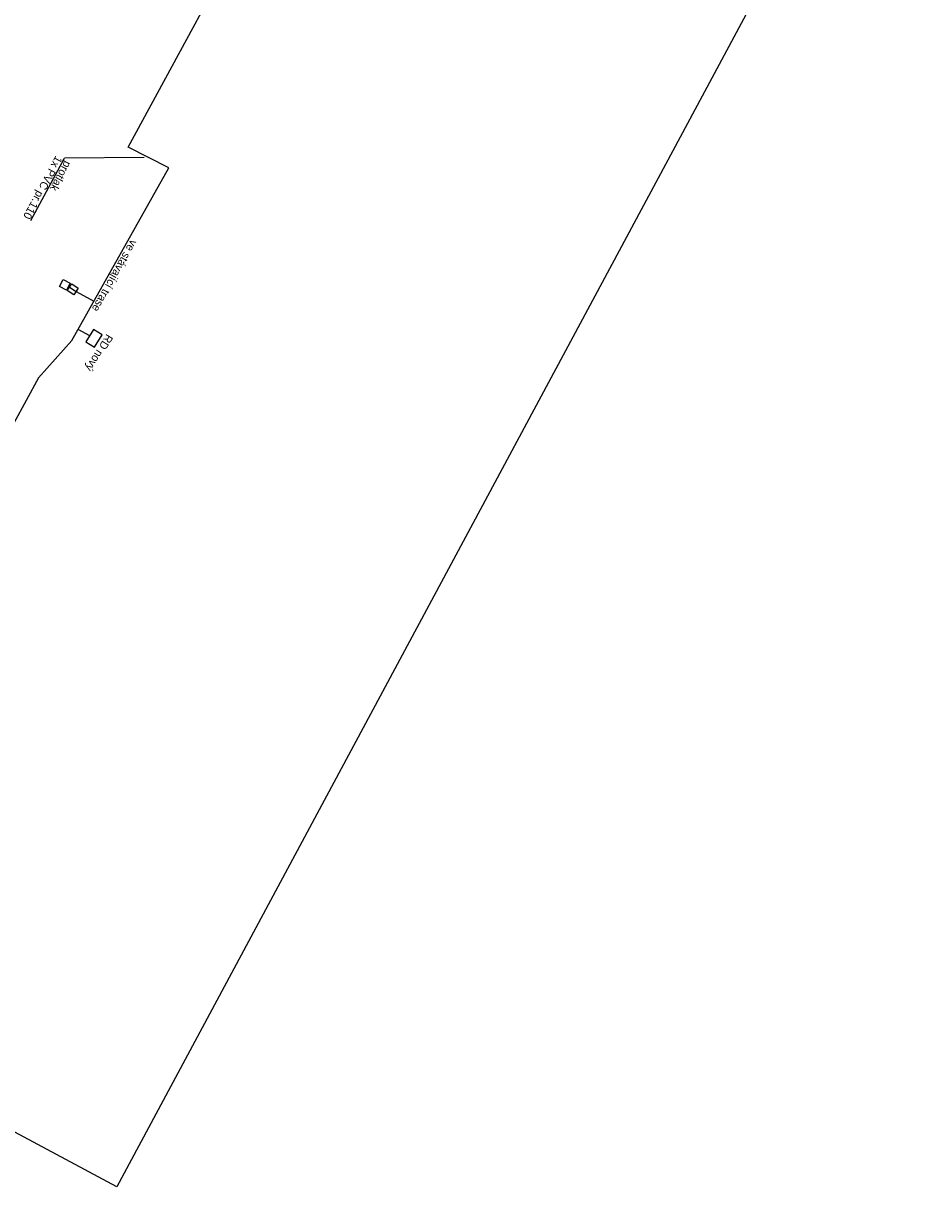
# Model space of a CAD drawing. Extents: x -795110 to -794650, y -1135846 to -1134690.
# Drawn here: x -794871.7 to -794649.8, y -1135200.1 to -1134909.4 of the extents above; entities that cross this region are included whole.
import ezdxf

# ---------------------------------------------------------------- set-up
doc = ezdxf.new("R2010")
doc.units = 0
for name, color, linetype in [('Kabelová trasa', 7, 'Continuous'), ('Popis trasy', 7, 'Continuous'), ('Prvky_zab_zar', 7, 'Continuous'), ('Ramecky', 7, 'Continuous'), ('Vrstva 3', 7, 'Continuous')]:
    doc.layers.add(name, color=color, linetype=linetype)

msp = doc.modelspace()

# ---------------------------------------------------------------- linework, layer by layer
at = {"layer": 'Kabelová trasa'}
for p, q in [((-794855.08, -1134987.47), (-794858.01, -1134985.89)), ((-794859.57, -1134988.66), (-794867.89, -1134997.98)), ((-794867.89, -1134997.98), (-794877.13, -1135014.95))]:
    msp.add_line(p, q, dxfattribs=at)
for points in [[(-794859.57, -1134988.66), (-794835.3, -1134945.55), (-794845.51, -1134940.37), (-794776.44, -1134813), (-794772.18, -1134815.08)], [(-794860.41, -1134975.21), (-794860.15, -1134975.35), (-794858.49, -1134976.45), (-794854.05, -1134978.87)]]:
    msp.add_lwpolyline(points, dxfattribs=at)
at = {"layer": 'Popis trasy'}
for p in [(-794869.76, -1134958.68), (-794841.5, -1134942.97)]:
    msp.add_line(p, (-794861.41, -1134943.12), dxfattribs=at)
at = {"layer": 'Prvky_zab_zar'}
msp.add_lwpolyline([(-794853.93, -1134990.33), (-794852.01, -1134987.28), (-794854.13, -1134985.95), (-794856.04, -1134989)], close=True, dxfattribs=at)
at = {"layer": 'Ramecky'}
msp.add_lwpolyline([(-795110.04, -1135059.75), (-794911.6, -1134689.59), (-794649.84, -1134829.91), (-794848.28, -1135200.08)], close=True, dxfattribs=at)
at = {"layer": 'Vrstva 3'}
for points in [[(-794862.65, -1134975.14), (-794861.7, -1134973.38), (-794859.94, -1134974.33), (-794860.89, -1134976.09)], [(-794860.71, -1134976.13), (-794859.57, -1134974.48), (-794857.93, -1134975.62), (-794859.07, -1134977.27)]]:
    msp.add_lwpolyline(points, close=True, dxfattribs=at)

# ---------------------------------------------------------------- texts
at = {"layer": 'Kabelová trasa'}
msp.add_text('ve stávající trase', height=2, rotation=240.6247, dxfattribs=at).set_placement((-794844.79, -1134963.28))
at = {"layer": 'Popis trasy'}
for s, p in [('1x PVC pr.110', (-794863.56, -1134942.35)), ('protlak', (-794861.3, -1134943.56))]:
    msp.add_text(s, height=2, rotation=241.8045, dxfattribs=at).set_placement(p)
at = {"layer": 'Prvky_zab_zar'}
msp.add_text('RD nový', height=2, rotation=237.836, dxfattribs=at).set_placement((-794850.83, -1134986.87))

doc.saveas('drawing.dxf')
